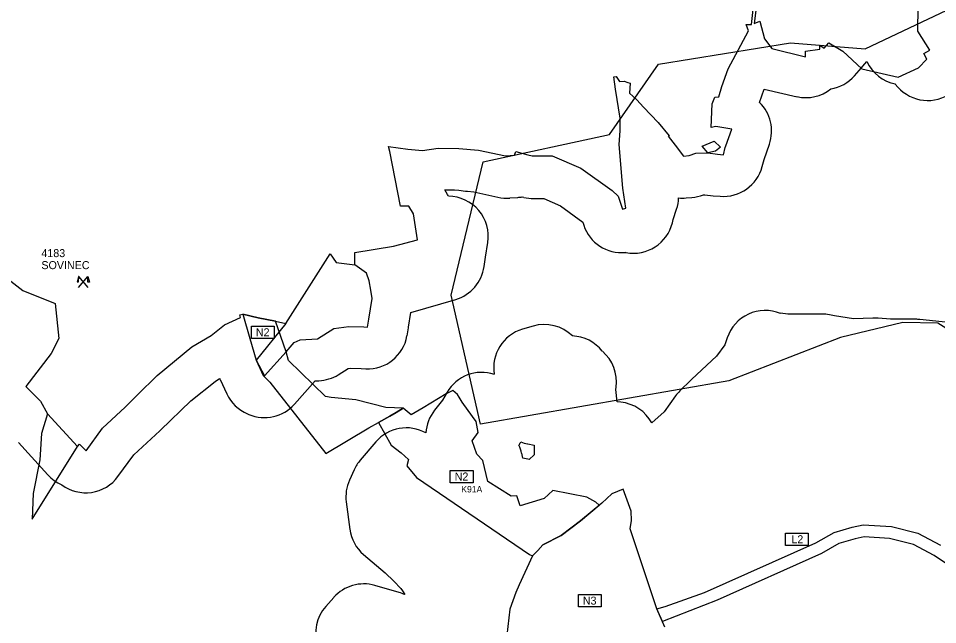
# Model space of a CAD drawing. Extents: x -547623 to -532764, y -1096714 to -1086523.
# Drawn here: x -545785 to -544637, y -1095151 to -1094393 of the extents above; entities that cross this region are included whole.
import ezdxf

# ---------------------------------------------------------------- set-up
doc = ezdxf.new("R2010")
doc.units = 0
for name, color, linetype in [('Vrstva 22', 7, 'Continuous'), ('Vrstva 23', 7, 'Continuous'), ('Vrstva 25', 7, 'Continuous'), ('Vrstva 27', 7, 'Continuous'), ('Vrstva 28', 7, 'Continuous'), ('Vrstva 32', 7, 'Continuous'), ('Vrstva 33', 7, 'Continuous'), ('Vrstva 36', 7, 'Continuous'), ('Vrstva 53', 7, 'Continuous')]:
    doc.layers.add(name, color=color, linetype=linetype)

msp = doc.modelspace()

# ---------------------------------------------------------------- linework, layer by layer
at = {"layer": 'Vrstva 22'}
msp.add_lwpolyline([(-544569.4, -1094608.5), (-544554.7, -1094768.3), (-544608.7, -1094791.9), (-544636.4, -1094774.2), (-544680.5, -1094773.3), (-544758.2, -1094792.2), (-544897.7, -1094846.4), (-545208, -1094900.4), (-545244.6, -1094739.1), (-545204.8, -1094572.8), (-545046.9, -1094538.4), (-544985.5, -1094450.5), (-544820.5, -1094424), (-544727.5, -1094431.4), (-544569.8, -1094356.5), (-544494.7, -1094387.2), (-544482, -1094546.9), (-544569.4, -1094608.5)], dxfattribs=at)
at = {"layer": 'Vrstva 23'}
for p, q in [((-545171.1, -1094617.8), (-545161.3, -1094617.1)), ((-545156, -1094616.4), (-545153.8, -1094616.9)), ((-545026.9, -1094685.7), (-545026.2, -1094685.9)), ((-544623.2, -1094773.5), (-544659.1, -1094769.7)), ((-545299.7, -1094790.2), (-545297.9, -1094780.1)), ((-545142.3, -1094777.9), (-545155.4, -1094781.8)), ((-545533.2, -1094844.8), (-545524.9, -1094862.6)), ((-544945.2, -1094845.4), (-544958.9, -1094858.9)), ((-545038.9, -1094857.1), (-545038.5, -1094854.2)), ((-545037.1, -1094872.5), (-545038.9, -1094857.1)), ((-545032.7, -1094873), (-545037.1, -1094872.5)), ((-545499.1, -1094887.4), (-545497.2, -1094888.2)), ((-545785.2, -1094923.2), (-545748.3, -1094963.9)), ((-545338.5, -1094922.6), (-545358.1, -1094945.5)), ((-545149, -1094925.2), (-545140.8, -1094926.6)), ((-545155, -1094942.9), (-545156.5, -1094936.7)), ((-545365.7, -1094957.4), (-545371.7, -1094970.5)), ((-545375.7, -1094997.7), (-545371.2, -1095031.9)), ((-545309.5, -1095110.9), (-545339.9, -1095102.1)), ((-545391.2, -1095116.9), (-545401.3, -1095128.2))]:
    msp.add_line(p, q, dxfattribs=at)
for points in [[(-544740.7, -1094465), (-544734.7, -1094458.3), (-544734.7, -1094458.3), (-544725.1, -1094447.3)], [(-544859.3, -1094498.4), (-544853.6, -1094481.9), (-544812.5, -1094491.2)], [(-544853.6, -1094569.5), (-544853.6, -1094569.5), (-544847.1, -1094550.5)], [(-544856, -1094578.5), (-544853.7, -1094569.7)], [(-545249, -1094613.6), (-545252.6, -1094607.5), (-545240.5, -1094607.4), (-545235.1, -1094608), (-545226.5, -1094609.1)], [(-545224.2, -1094609.3), (-545216.2, -1094610), (-545186.1, -1094616.8)], [(-545141.4, -1094618.5), (-545128.7, -1094618.6), (-545107.8, -1094627.5), (-545080.2, -1094648.2), (-545079, -1094651.8)], [(-544951.1, -1094617.8), (-544944.1, -1094617.2)], [(-544929.6, -1094613.8), (-544929.2, -1094613.8)], [(-544929.2, -1094613.8), (-544927.7, -1094614), (-544917.1, -1094614.9)], [(-544917.1, -1094614.9), (-544908.5, -1094615.6)], [(-544968.1, -1094648.7), (-544967.1, -1094644.7), (-544962.9, -1094631.8)], [(-545203.4, -1094703.6), (-545201.7, -1094691.7), (-545198.8, -1094673.5)], [(-545297.8, -1094779.1), (-545294.9, -1094760.9), (-545238.9, -1094744.5)], [(-544781.3, -1094762.9), (-544824, -1094762.8), (-544833.3, -1094761.9)], [(-544717.9, -1094767.8), (-544741.8, -1094769), (-544765.9, -1094765), (-544772, -1094763.8)], [(-544664.2, -1094769.4), (-544695.9, -1094769.2), (-544711.2, -1094767.9)], [(-544899.7, -1094792.6), (-544902.5, -1094801.3), (-544913.1, -1094815.5), (-544944.1, -1094844.4)], [(-545385.6, -1094838.7), (-545373.2, -1094830.9), (-545370.1, -1094830.5), (-545357.1, -1094831.1), (-545351.3, -1094831.4)], [(-545607.7, -1094908.1), (-545569.7, -1094871.3), (-545539.4, -1094847), (-545533.8, -1094843.5)], [(-545440.3, -1094875.4), (-545414.5, -1094846.4), (-545409.9, -1094846.2)], [(-545249.7, -1094860.6), (-545255.4, -1094870.5), (-545265.4, -1094883.1)], [(-544964.4, -1094865.2), (-544978.6, -1094885), (-544993.9, -1094899)], [(-545660.8, -1094965.8), (-545640.9, -1094938.8), (-545608.5, -1094908.9)], [(-545140.8, -1094926.6), (-545140.7, -1094938.8), (-545147, -1094944.8)], [(-545353.9, -1095063.5), (-545327.1, -1095086.2), (-545316.4, -1095096.7), (-545307.6, -1095106), (-545305.3, -1095108.6), (-545302.5, -1095113.5)]]:
    msp.add_lwpolyline(points, dxfattribs=at)
for centre, start, end in [((-544679.7, -1094426.3), 204.7377, 258.4749), ((-544778.3, -1094432.2), 279.2896, 318.874), ((-544801.5, -1094442.4), 257.2237, 308.64), ((-544649.3, -1094445.9), 216.0604, 301.6028), ((-544894.3, -1094534.1), 340.9329, 45.5887), ((-544902, -1094556.9), 345.2341, 345.4034), ((-544904.4, -1094565.8), 265.2805, 345.2341), ((-545220.3, -1094559.5), 262.8422, 265.5482), ((-545291.9, -1094639.2), 28.0844, 30.8014), ((-545248.2, -1094665.7), 350.9988, 89.5729), ((-545175.1, -1094568), 257.2965, 274.5094), ((-545165.2, -1094567.2), 274.5094, 280.6167), ((-545141.2, -1094568.6), 255.3542, 269.6727), ((-545010.4, -1094616.2), 341.868, 358.3476), ((-544955.1, -1094567.9), 263.8452, 274.5935), ((-544948.1, -1094567.4), 274.5935, 291.7842), ((-544913, -1094565.1), 265.2187, 265.2805), ((-545031.6, -1094636), 198.4349, 275.4123), ((-545016.7, -1094636.8), 259.0651, 346.243), ((-545252.9, -1094696.5), 286.2632, 351.883), ((-544852.2, -1094808.3), 67.8553, 161.7541), ((-544781.5, -1094812.9), 79.1018, 89.8208), ((-544715.4, -1094817.8), 85.22, 92.8517), ((-544664.5, -1094819.4), 83.8546, 89.7273), ((-545347.2, -1094771.4), 349.8753, 351.1317), ((-545141.4, -1094829.7), 106.3423, 189.7566), ((-545128.2, -1094825.9), 45.4875, 106.3423), ((-545349, -1094781.4), 267.3529, 349.8753), ((-545095.1, -1094840.2), 38.1, 87.853), ((-545088.1, -1094847.4), 352.2219, 49.644), ((-545412, -1094796.2), 272.4263, 301.8754), ((-545206.4, -1094885.7), 71.6112, 149.9349), ((-545487.9, -1094823.6), 203.4847, 205.119), ((-544910.1, -1094881), 132.8776, 134.5572), ((-545479.6, -1094841.4), 205.119, 247.058), ((-544923.8, -1094894.5), 134.5572, 144.1781), ((-545037.9, -1094922.7), 28.3425, 83.9808), ((-545477.7, -1094842.2), 247.058, 318.3629), ((-545226.2, -1094914.2), 141.5623, 176.8977), ((-545642.5, -1094872.2), 312.7352, 314.0315), ((-545300.6, -1094955.1), 60.7996, 139.4008), ((-545202.6, -1094900.8), 328.5486, 333.9231), ((-545205.2, -1094948.3), 13.3744, 25.3803), ((-545140.2, -1094875.9), 249.4518, 259.8059), ((-545162.3, -1094992.4), 72.1323, 81.6307), ((-545320.2, -1094978), 139.4008, 155.6744), ((-545711.3, -1094930.3), 222.2028, 246.7596), ((-545701.1, -1094936.2), 233.1738, 323.698), ((-545326.1, -1094991.1), 155.6744, 187.4959), ((-545321.6, -1095025.3), 187.4959, 229.7837), ((-545353.8, -1095150.1), 73.831, 138.3665), ((-545323.4, -1095158.9), 65.2982, 73.831), ((-545363.9, -1095161.4), 138.3665, 198.3511)]:
    msp.add_arc(centre, 50, start, end, dxfattribs=at)
at = {"layer": 'Vrstva 25'}
for points in [[(-544862, -1094366.4), (-544866.1, -1094399.8), (-544859.1, -1094397), (-544853, -1094418.9), (-544843.8, -1094430.8), (-544801.9, -1094441.4), (-544801.8, -1094434.1), (-544784.2, -1094431.6), (-544783.9, -1094426.9), (-544778.4, -1094430.5), (-544772.6, -1094423.7), (-544755.4, -1094434.1), (-544731.5, -1094456.2), (-544686.3, -1094466.7), (-544660.7, -1094455), (-544650.4, -1094444.2), (-544654, -1094437.3), (-544646.4, -1094433.2), (-544661.7, -1094409.1), (-544660.8, -1094347.9)], [(-545364.8, -1094701.3), (-545365.1, -1094686), (-545316.5, -1094677.8), (-545286.7, -1094670.1), (-545291.7, -1094637.6), (-545297.3, -1094628.1), (-545308, -1094627.9), (-545321.1, -1094559.7), (-545322.9, -1094553.3), (-545298.8, -1094556.8), (-545280.4, -1094558.3), (-545260.8, -1094555.6), (-545234.9, -1094555.8), (-545210.4, -1094558.2), (-545176.6, -1094564.9), (-545165.6, -1094564.3), (-545163.6, -1094559.6), (-545148.6, -1094563.8), (-545143.4, -1094565.3), (-545118.4, -1094565.3), (-545082.5, -1094580.4), (-545043.5, -1094608.6), (-545036, -1094615.7), (-545030.7, -1094631.9), (-545026.2, -1094630.6), (-545030, -1094605.6), (-545034.6, -1094550.8), (-545033.3, -1094533.8), (-545033.5, -1094518.2), (-545039.1, -1094481.9), (-545041.3, -1094466.5), (-545038.3, -1094465.8), (-545034.1, -1094472.3), (-545028.6, -1094471.9), (-545024, -1094473.4), (-545021.1, -1094474.4), (-545021.8, -1094486.9), (-545012.8, -1094495.3), (-545004.3, -1094504.2), (-544986, -1094523.4), (-544972.1, -1094540), (-544973.6, -1094540.4), (-544964.9, -1094551.6), (-544954.3, -1094565.5), (-544947.3, -1094564.8), (-544938.9, -1094561.8), (-544924, -1094561.5), (-544930.9, -1094553.1), (-544916.2, -1094546.8), (-544908, -1094554.2), (-544914.3, -1094559.1), (-544924, -1094561.5), (-544911.7, -1094562.9), (-544904.2, -1094563.7), (-544902.1, -1094554.5), (-544901.5, -1094552.6), (-544893.9, -1094531.9), (-544913.9, -1094528.3), (-544919.6, -1094529.8), (-544918.4, -1094500.1), (-544915.1, -1094491.9), (-544910.3, -1094491.2), (-544906.4, -1094478.3), (-544898.7, -1094456.2), (-544873, -1094408.8), (-544876.1, -1094400.8), (-544869.2, -1094401.1), (-544865.7, -1094366.4)], [(-545345, -1094732.9), (-545346.9, -1094721.3), (-545350.3, -1094711.6), (-545364.8, -1094701.3)], [(-545794.8, -1094721.6), (-545779.8, -1094733.3), (-545739.1, -1094749.6), (-545734.6, -1094793.4), (-545744.1, -1094812.1), (-545776.1, -1094853.2), (-545757.5, -1094871.9), (-545748.7, -1094887.7), (-545756.3, -1094912), (-545758.5, -1094944.9), (-545766.7, -1094987.3), (-545768, -1095019.2), (-545711.5, -1094928.4), (-545708.9, -1094925.6), (-545700.5, -1094933.9), (-545680, -1094905.5), (-545652, -1094879.2), (-545636.5, -1094863.8), (-545611.7, -1094839.5), (-545568.6, -1094803.9), (-545544.4, -1094789.6), (-545527.8, -1094776.3), (-545507.6, -1094767), (-545508.6, -1094763.8), (-545504.7, -1094763), (-545485.5, -1094767.6), (-545463.9, -1094771.9), (-545451.2, -1094774.5)], [(-545440.8, -1094798.6), (-545433.3, -1094795), (-545411.4, -1094794), (-545391.2, -1094780.8), (-545372.4, -1094778.3), (-545353.7, -1094778.9), (-545348.9, -1094779.1), (-545347.3, -1094769.4), (-545343.3, -1094743.6), (-545345, -1094732.9)], [(-545451.2, -1094774.5), (-545488.2, -1094820.5), (-545477.6, -1094840.2), (-545450.7, -1094809.9), (-545440.8, -1094798.6)]]:
    msp.add_lwpolyline(points, dxfattribs=at)
at = {"layer": 'Vrstva 27'}
for points in [[(-544862, -1094366.4), (-544866.1, -1094399.8), (-544859.1, -1094397), (-544853, -1094418.9), (-544843.8, -1094430.8), (-544801.9, -1094441.4), (-544801.8, -1094434.1), (-544784.2, -1094431.6), (-544783.9, -1094426.9), (-544778.4, -1094430.5), (-544772.6, -1094423.7), (-544755.4, -1094434.1), (-544731.5, -1094456.2), (-544686.3, -1094466.7), (-544660.7, -1094455), (-544650.4, -1094444.2), (-544654, -1094437.3), (-544646.4, -1094433.2), (-544661.7, -1094409.1), (-544660.8, -1094347.9)], [(-545794.8, -1094721.6), (-545779.8, -1094733.3), (-545739.1, -1094749.6), (-545734.6, -1094793.4), (-545744.1, -1094812.1), (-545776.1, -1094853.2), (-545757.5, -1094871.9), (-545748.7, -1094887.7), (-545711.5, -1094928.4), (-545708.9, -1094925.6), (-545700.5, -1094933.9), (-545680, -1094905.5), (-545652, -1094879.2), (-545636.5, -1094863.8), (-545611.7, -1094839.5), (-545568.6, -1094803.9), (-545544.4, -1094789.6), (-545527.8, -1094776.3), (-545507.6, -1094767), (-545508.6, -1094763.8), (-545504.7, -1094763), (-545485.5, -1094767.6), (-545463.9, -1094771.9), (-545451.2, -1094774.5), (-545395.9, -1094687.7), (-545388.4, -1094698.5), (-545364.8, -1094701.3), (-545365.1, -1094686), (-545316.5, -1094677.8), (-545286.7, -1094670.1), (-545291.7, -1094637.6), (-545297.3, -1094628.1), (-545308, -1094627.9), (-545321.1, -1094559.7), (-545322.9, -1094553.3), (-545298.8, -1094556.8), (-545280.4, -1094558.3), (-545260.8, -1094555.6), (-545234.9, -1094555.8), (-545210.4, -1094558.2), (-545176.6, -1094564.9), (-545165.6, -1094564.3), (-545163.6, -1094559.6), (-545148.6, -1094563.8), (-545143.4, -1094565.3), (-545118.4, -1094565.3), (-545082.5, -1094580.4), (-545043.5, -1094608.6), (-545036, -1094615.7), (-545030.7, -1094631.9), (-545026.2, -1094630.6), (-545030, -1094605.6), (-545034.6, -1094550.8), (-545033.3, -1094533.8), (-545033.5, -1094518.2), (-545039.1, -1094481.9), (-545041.3, -1094466.5), (-545038.3, -1094465.8), (-545034.1, -1094472.3), (-545028.6, -1094471.9), (-545024, -1094473.4), (-545021.1, -1094474.4), (-545021.8, -1094486.9), (-545012.8, -1094495.3), (-545004.3, -1094504.2), (-544986, -1094523.4), (-544972.1, -1094540), (-544973.6, -1094540.4), (-544964.9, -1094551.6), (-544954.3, -1094565.5), (-544947.3, -1094564.8), (-544938.9, -1094561.8), (-544924, -1094561.5), (-544930.9, -1094553.1), (-544916.2, -1094546.8), (-544908, -1094554.2), (-544914.3, -1094559.1), (-544924, -1094561.5), (-544911.7, -1094562.9), (-544904.2, -1094563.7), (-544902.1, -1094554.5), (-544901.5, -1094552.6), (-544893.9, -1094531.9), (-544913.9, -1094528.3), (-544919.6, -1094529.8), (-544918.4, -1094500.1), (-544915.1, -1094491.9), (-544910.3, -1094491.2), (-544906.4, -1094478.3), (-544898.7, -1094456.2), (-544873, -1094408.8), (-544876.1, -1094400.8), (-544869.2, -1094401.1), (-544865.7, -1094366.4)]]:
    msp.add_lwpolyline(points, dxfattribs=at)
at = {"layer": 'Vrstva 28'}
for points in [[(-545485.5, -1094767.6), (-545504.7, -1094763), (-545496, -1094793.4), (-545488.2, -1094820.5), (-545479.4, -1094839.5), (-545477.6, -1094840.2), (-545450.7, -1094809.9), (-545463.9, -1094771.9), (-545485.5, -1094767.6)], [(-545335.4, -1094898.4), (-545321.2, -1094890.5), (-545313.1, -1094885.7), (-545304.5, -1094880.5), (-545326.2, -1094879.8), (-545363.5, -1094870.2), (-545394.6, -1094867.1), (-545401.5, -1094865.8), (-545447.7, -1094820.9), (-545450.7, -1094809.9), (-545477.6, -1094840.2), (-545479.4, -1094839.5), (-545471.1, -1094847.8), (-545401.1, -1094937.1), (-545347.4, -1094905.2), (-545335.4, -1094898.4)], [(-545304.5, -1094880.5), (-545313.1, -1094885.7), (-545321.2, -1094890.5), (-545335.4, -1094898.4), (-545319.4, -1094926.9), (-545307, -1094936.2), (-545297.8, -1094944.6), (-545300.1, -1094952.7), (-545288, -1094967.2), (-545146.7, -1095063.3), (-545142.8, -1095065.2), (-545136.3, -1095058.2), (-545130.2, -1095051.2), (-545107.3, -1095039.6), (-545082.9, -1095021.3), (-545059.6, -1095001.9), (-545064, -1094997.8), (-545074.9, -1094991.6), (-545117.4, -1094983.3), (-545128.4, -1094993.3), (-545158.4, -1095002.7), (-545162.6, -1094990.2), (-545169.8, -1094990.4), (-545198.8, -1094972.1), (-545205.2, -1094945.7), (-545212.7, -1094937.8), (-545218.2, -1094921.3), (-545210.7, -1094910.9), (-545213.4, -1094897.3), (-545217.9, -1094891), (-545231, -1094872.8), (-545234.5, -1094866.7), (-545236.8, -1094863.5), (-545242.3, -1094858.3), (-545250.8, -1094862.5), (-545279.4, -1094880.1), (-545294.7, -1094888.6), (-545304.5, -1094880.5)]]:
    msp.add_lwpolyline(points, dxfattribs=at)
at = {"layer": 'Vrstva 32'}
msp.add_lwpolyline([(-544977.6, -1095154), (-544987.5, -1095131.1), (-545021.1, -1095031.3), (-545019.2, -1095020.9), (-545019.9, -1095009.1), (-545029.6, -1094981.6), (-545043.9, -1094987.4), (-545056.3, -1094999.1), (-545082.9, -1095021.3), (-545107.3, -1095039.6), (-545130.2, -1095051.2), (-545136.3, -1095058.2), (-545142.8, -1095065.2), (-545159.6, -1095101.2), (-545163.6, -1095110.7), (-545171.2, -1095131.7), (-545175.2, -1095164.2)], dxfattribs=at)
at = {"layer": 'Vrstva 33'}
for points in [[(-544927.9, -1095111), (-544788.9, -1095048.7), (-544766.1, -1095035.7), (-544743.6, -1095029), (-544729.7, -1095026.3), (-544694.6, -1095028.5), (-544661.7, -1095036.7), (-544633.2, -1095051.5)], [(-544612.7, -1095083.9), (-544641, -1095064.4), (-544667.1, -1095050.9), (-544696.9, -1095043.4), (-544728.7, -1095041.4), (-544740, -1095043.6), (-544760.2, -1095049.6), (-544782.1, -1095062.1), (-544912.2, -1095120.4), (-544980.6, -1095146.9), (-544987.5, -1095131.1), (-544977.1, -1095128.4), (-544927.9, -1095111)]]:
    msp.add_lwpolyline(points, dxfattribs=at)
at = {"layer": 'Vrstva 36'}
for points in [[(-545494.1, -1094777.9), (-545465.5, -1094777.9), (-545465.5, -1094793.3), (-545494.1, -1094793.3)], [(-545245.7, -1094958.2), (-545217.1, -1094958.2), (-545217.1, -1094973.7), (-545245.7, -1094973.7)], [(-544827.1, -1095036.6), (-544798.4, -1095036.6), (-544798.4, -1095052.1), (-544827.1, -1095052.1)], [(-545085.7, -1095113.3), (-545057.1, -1095113.3), (-545057.1, -1095128.7), (-545085.7, -1095128.7)]]:
    msp.add_lwpolyline(points, close=True, dxfattribs=at)
at = {"layer": 'Vrstva 53'}
for p, q in [((-545709.9, -1094715.8), (-545710, -1094715.8)), ((-545698.4, -1094715.9), (-545698.4, -1094715.9))]:
    msp.add_line(p, q, dxfattribs=at)
for points in [[(-545710, -1094715.8), (-545711.9, -1094722.7), (-545710, -1094722.7), (-545709.9, -1094715.8)], [(-545710.3, -1094729.8), (-545698.4, -1094715.9)], [(-545698, -1094729.6), (-545709.9, -1094715.8), (-545710, -1094715.8)], [(-545698.4, -1094715.9), (-545696.4, -1094722.9), (-545698.4, -1094722.9), (-545698.4, -1094715.9)]]:
    msp.add_lwpolyline(points, dxfattribs=at)

# ---------------------------------------------------------------- texts
at = {"layer": 'Vrstva 36'}
for s, height, p in [('N2', 10, (-545488.6, -1094790.6)), ('N2', 10, (-545240.2, -1094970.9)), ('K91A', 8, (-545231.9, -1094985.8)), ('L2', 10, (-544819.6, -1095049.3)), ('N3', 10, (-545080.1, -1095126))]:
    msp.add_text(s, height=height, dxfattribs=at).set_placement(p)
at = {"layer": 'Vrstva 53'}
for s, p in [('4183', (-545756.5, -1094691.7)), ('SOVINEC', (-545756.5, -1094706.7))]:
    msp.add_text(s, height=10, dxfattribs=at).set_placement(p)

doc.saveas('drawing.dxf')
